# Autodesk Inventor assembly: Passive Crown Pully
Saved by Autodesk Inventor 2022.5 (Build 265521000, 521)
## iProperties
Created: 2025-01
Part Number: Passive Crown Pully
Document SubType Name: Assembly
Designer: AdminForWorker
Title: Passive Crown Pully v8
Author: AdminForWorker
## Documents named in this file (5)
- c:\worker\convert-fusion-r06-cosv3\tmp\job-1\32\temp\files\1fa427a3-f06c-414d-b039-a0eb315ba580\2a3fdf13-9ba7-48eb-88a5-672a8a7e5615.iam
- c:\worker\convert-fusion-r06-cosv3\tmp\job-1\32\temp\files\1fa427a3-f06c-414d-b039-a0eb315ba580\Bearing 4_12 ID_OD v1.ipt
- c:\worker\convert-fusion-r06-cosv3\tmp\job-1\32\temp\files\1fa427a3-f06c-414d-b039-a0eb315ba580\32x4 mm Dowel v1.ipt
- c:\worker\convert-fusion-r06-cosv3\tmp\job-1\32\temp\files\1fa427a3-f06c-414d-b039-a0eb315ba580\Component1.ipt
- c:\worker\convert-fusion-r06-cosv3\tmp\job-1\32\temp\files\1fa427a3-f06c-414d-b039-a0eb315ba580\Component2.ipt
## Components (5 placed, 4 different names)
1. Bearing 4/12 ID/OD v1:1
2. 32x4 mm Dowel v1:1
3. Bearing 4/12 ID/OD v1:2
4. Component1:1
5. Component2:1
